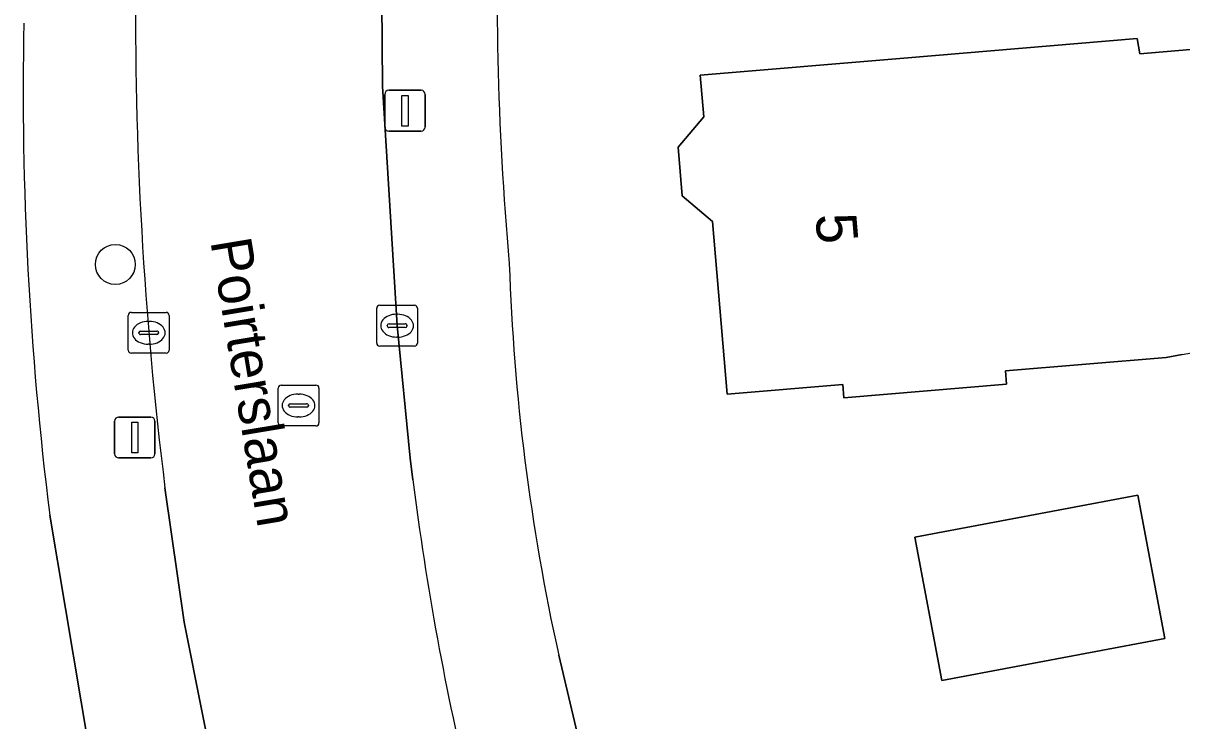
# Model space of a CAD drawing. Extents: x 161347 to 161881, y 382161 to 382804.
# Drawn here: x 161469.37 to 161497.74, y 382343.81 to 382360.88 of the extents above; entities that cross this region are included whole.
import ezdxf

# ---------------------------------------------------------------- set-up
doc = ezdxf.new("R2010")
doc.units = 0
for name, color, linetype in [('IMGEO_Boom', 7, 'Continuous'), ('IMGEO_Erf', 7, 'Continuous'), ('IMGEO_Kolk', 7, 'Continuous'), ('IMGEO_Lichtmast', 7, 'Continuous'), ('IMGEO_Openbare_ruimte_label', 7, 'Continuous'), ('IMGEO_Pand', 7, 'Continuous'), ('IMGEO_Pand_nummerreeks', 7, 'Continuous'), ('IMGEO_Rijbaan_lokaal_open', 7, 'Continuous'), ('IMGEO_Rioolput', 7, 'Continuous'), ('IMGEO_Voetpad_open', 7, 'Continuous')]:
    doc.layers.add(name, color=color, linetype=linetype)

msp = doc.modelspace()

# ---------------------------------------------------------------- linework, layer by layer
at = {"layer": 'IMGEO_Boom'}
msp.add_circle((161471.631, 382354.973), 0.489, dxfattribs=at)
at = {"layer": 'IMGEO_Erf'}
for points in [[(161497.75, 382352.769), (161497.358, 382352.698), (161493.425, 382352.37), (161493.453, 382352.045), (161489.468, 382351.71), (161489.441, 382352.035), (161486.61, 382351.797), (161486.255, 382356.023), (161485.507, 382356.655), (161485.408, 382357.84), (161486.037, 382358.585), (161485.952, 382359.604), (161490.935, 382360.023), (161496.653, 382360.502), (161496.711, 382360.131), (161498.911, 382360.315)], [(161471.178, 382341.99), (161470.024, 382348.841)], [(161482.485, 382345.416), (161483.643, 382340.539), (161484.991, 382335.711)]]:
    msp.add_lwpolyline(points, dxfattribs=at)
msp.add_lwpolyline([(161497.326, 382345.818), (161491.863, 382344.795), (161491.206, 382348.304), (161496.669, 382349.327)], close=True, dxfattribs=at)
for centre, radius, start, end in [((161557.326, 382361.781), 76.351, 177.58362, 185.0968), ((161553.635, 382359.287), 84.261, 178.91872, 187.12135), ((161533.467, 382356.71), 52.218, 181.8793, 192.4914)]:
    msp.add_arc(centre, radius, start, end, dxfattribs=at)
at = {"layer": 'IMGEO_Kolk'}
for p, q in [((161478.104, 382353.975), (161478.956, 382353.975)), ((161471.948, 382352.875), (161471.948, 382353.727)), ((161472.023, 382353.801), (161472.875, 382353.801)), ((161472.949, 382353.727), (161472.949, 382352.875)), ((161478.029, 382353.049), (161478.029, 382353.901)), ((161478.517, 382353.755), (161478.542, 382353.755)), ((161479.03, 382353.901), (161479.03, 382353.049)), ((161472.436, 382353.581), (161472.461, 382353.581)), ((161478.288, 382353.469), (161478.288, 382353.481)), ((161478.726, 382353.432), (161478.328, 382353.432)), ((161478.331, 382353.518), (161478.729, 382353.518)), ((161478.772, 382353.481), (161478.772, 382353.469)), ((161472.207, 382353.295), (161472.207, 382353.307)), ((161472.645, 382353.258), (161472.247, 382353.258)), ((161472.25, 382353.344), (161472.648, 382353.344)), ((161472.691, 382353.307), (161472.691, 382353.295)), ((161478.54, 382353.195), (161478.515, 382353.195)), ((161472.459, 382353.021), (161472.434, 382353.021)), ((161478.956, 382352.975), (161478.104, 382352.975)), ((161472.875, 382352.801), (161472.023, 382352.801))]:
    msp.add_line(p, q, dxfattribs=at)
for points in [[(161478.104, 382353.975), (161478.956, 382353.975)], [(161471.948, 382352.875), (161471.948, 382353.727)], [(161472.023, 382353.801), (161472.875, 382353.801)], [(161472.949, 382353.727), (161472.949, 382352.875)], [(161478.029, 382353.049), (161478.029, 382353.901)], [(161479.03, 382353.901), (161479.03, 382353.049)], [(161478.956, 382352.975), (161478.104, 382352.975)], [(161472.875, 382352.801), (161472.023, 382352.801)]]:
    msp.add_lwpolyline(points, dxfattribs=at)
for centre, radius, start, end in [((161478.106, 382353.899), 0.0765, 91.552, 178.448), ((161478.106, 382353.899), 0.0765, 91.552, 178.448), ((161478.954, 382353.899), 0.0765, 1.552, 88.448), ((161478.954, 382353.899), 0.0765, 1.552, 88.448), ((161472.025, 382353.725), 0.0765, 91.552, 178.448), ((161472.025, 382353.725), 0.0765, 91.552, 178.448), ((161472.873, 382353.725), 0.0765, 1.552, 88.448), ((161472.873, 382353.725), 0.0765, 1.552, 88.448), ((161478.328, 382353.478), 0.0403, 85.8775, 175.7526), ((161478.325, 382353.468), 0.0366, 178.938, 274.7102), ((161478.729, 382353.475), 0.043, 264.8664, 352.4533), ((161478.733, 382353.48), 0.0386, 1.7309, 96.639), ((161472.247, 382353.304), 0.0403, 85.8775, 175.7526), ((161472.244, 382353.294), 0.0366, 178.938, 274.7102), ((161472.648, 382353.301), 0.043, 264.8664, 352.4533), ((161472.652, 382353.306), 0.0386, 1.7309, 96.639), ((161472.025, 382352.877), 0.0765, 181.552, 268.448), ((161472.025, 382352.877), 0.0765, 181.552, 268.448), ((161472.873, 382352.877), 0.0765, 271.552, 358.448), ((161472.873, 382352.877), 0.0765, 271.552, 358.448), ((161478.106, 382353.051), 0.0765, 181.552, 268.448), ((161478.106, 382353.051), 0.0765, 181.552, 268.448), ((161478.954, 382353.051), 0.0765, 271.552, 358.448), ((161478.954, 382353.051), 0.0765, 271.552, 358.448)]:
    msp.add_arc(centre, radius, start, end, dxfattribs=at)
for centre, major_axis, ratio, start_param, end_param in [((161478.516, 382353.475), (-0.387, 0.002), 0.722429, 4.712389, 7.853982), ((161478.541, 382353.475), (-0.39, 0.002), 0.717154, 1.570796, 4.712389), ((161472.435, 382353.301), (-0.387, 0.002), 0.722429, 4.712389, 7.853982), ((161472.46, 382353.301), (-0.39, 0.002), 0.717154, 1.570796, 4.712389)]:
    msp.add_ellipse(centre, major_axis=major_axis, ratio=ratio, start_param=start_param, end_param=end_param, dxfattribs=at)
at = {"layer": 'IMGEO_Lichtmast'}
for p, q in [((161478.227, 382358.335), (161478.227, 382359.135)), ((161478.227, 382359.135), (161478.227, 382358.335)), ((161478.327, 382359.235), (161479.117, 382359.235)), ((161479.117, 382359.235), (161478.327, 382359.235)), ((161479.217, 382359.135), (161479.217, 382358.335)), ((161479.217, 382358.335), (161479.217, 382359.135)), ((161479.117, 382358.235), (161478.327, 382358.235)), ((161478.327, 382358.235), (161479.117, 382358.235)), ((161471.611, 382350.34), (161471.611, 382351.14)), ((161471.611, 382351.14), (161471.611, 382350.34)), ((161471.711, 382351.24), (161472.501, 382351.24)), ((161472.501, 382351.24), (161471.711, 382351.24)), ((161472.601, 382351.14), (161472.601, 382350.34)), ((161472.601, 382350.34), (161472.601, 382351.14)), ((161472.501, 382350.24), (161471.711, 382350.24)), ((161471.711, 382350.24), (161472.501, 382350.24))]:
    msp.add_line(p, q, dxfattribs=at)
for points in [[(161478.647, 382359.11), (161478.797, 382359.11), (161478.797, 382358.36), (161478.647, 382358.36), (161478.647, 382359.11)], [(161472.031, 382351.115), (161472.181, 382351.115), (161472.181, 382350.365), (161472.031, 382350.365), (161472.031, 382351.115)]]:
    msp.add_lwpolyline(points, dxfattribs=at)
for centre, start, end in [((161478.327, 382359.135), 90, 180), ((161478.327, 382359.135), 90, 180), ((161479.117, 382359.135), 0, 90), ((161479.117, 382359.135), 360, 90), ((161478.327, 382358.335), 180, 270), ((161478.327, 382358.335), 180, 270), ((161479.117, 382358.335), 270, 0), ((161479.117, 382358.335), 270, 0), ((161471.711, 382351.14), 90, 180), ((161471.711, 382351.14), 90, 180), ((161472.501, 382351.14), 0, 90), ((161472.501, 382351.14), 360, 90), ((161471.711, 382350.34), 180, 270), ((161471.711, 382350.34), 180, 270), ((161472.501, 382350.34), 270, 0), ((161472.501, 382350.34), 270, 0)]:
    msp.add_arc(centre, 0.1, start, end, dxfattribs=at)
at = {"layer": 'IMGEO_Pand'}
for points in [[(161497.75, 382352.769), (161497.752, 382352.769), (161499.52, 382353.085), (161499.257, 382356.205), (161498.911, 382360.315), (161496.711, 382360.131), (161496.653, 382360.502), (161490.935, 382360.023), (161485.952, 382359.604), (161486.037, 382358.585), (161485.408, 382357.84), (161485.507, 382356.655), (161486.255, 382356.023), (161486.61, 382351.797), (161489.441, 382352.035), (161489.468, 382351.71), (161493.453, 382352.045), (161493.425, 382352.37), (161497.358, 382352.698)], [(161491.863, 382344.795), (161497.326, 382345.818), (161496.669, 382349.327), (161491.206, 382348.304)]]:
    msp.add_lwpolyline(points, close=True, dxfattribs=at)
at = {"layer": 'IMGEO_Rijbaan_lokaal_open'}
for points in [[(161478.913, 382349.703), (161478.847, 382350.23), (161478.529, 382353.479), (161478.171, 382359.336), (161478.141, 382363.489)], [(161472.846, 382349.505), (161473.315, 382346.221), (161474.229, 382341.636)]]:
    msp.add_lwpolyline(points, dxfattribs=at)
for centre, radius, start, end in [((161565.952, 382361.125), 93.828, 179.39336, 187.11372), ((161550.911, 382358.887), 72.581, 187.26923, 193.48629)]:
    msp.add_arc(centre, radius, start, end, dxfattribs=at)
at = {"layer": 'IMGEO_Rioolput'}
for p, q in [((161475.69, 382352.021), (161476.542, 382352.021)), ((161475.615, 382351.095), (161475.615, 382351.947)), ((161476.103, 382351.801), (161476.128, 382351.801)), ((161476.616, 382351.947), (161476.616, 382351.095)), ((161475.874, 382351.515), (161475.874, 382351.527)), ((161476.312, 382351.478), (161475.914, 382351.478)), ((161475.917, 382351.564), (161476.315, 382351.564)), ((161476.358, 382351.527), (161476.358, 382351.515)), ((161476.126, 382351.241), (161476.101, 382351.241)), ((161476.542, 382351.021), (161475.69, 382351.021))]:
    msp.add_line(p, q, dxfattribs=at)
for points in [[(161475.69, 382352.021), (161476.542, 382352.021)], [(161475.615, 382351.095), (161475.615, 382351.947)], [(161476.616, 382351.947), (161476.616, 382351.095)], [(161476.542, 382351.021), (161475.69, 382351.021)]]:
    msp.add_lwpolyline(points, dxfattribs=at)
for centre, radius, start, end in [((161475.692, 382351.945), 0.0765, 91.552, 178.448), ((161475.692, 382351.945), 0.0765, 91.552, 178.448), ((161476.54, 382351.945), 0.0765, 1.552, 88.448), ((161476.54, 382351.945), 0.0765, 1.552, 88.448), ((161475.914, 382351.524), 0.0403, 85.8775, 175.7526), ((161475.911, 382351.514), 0.0366, 178.938, 274.7102), ((161476.315, 382351.521), 0.043, 264.8664, 352.4533), ((161476.319, 382351.526), 0.0386, 1.7309, 96.639), ((161475.692, 382351.097), 0.0765, 181.552, 268.448), ((161475.692, 382351.097), 0.0765, 181.552, 268.448), ((161476.54, 382351.097), 0.0765, 271.552, 358.448), ((161476.54, 382351.097), 0.0765, 271.552, 358.448)]:
    msp.add_arc(centre, radius, start, end, dxfattribs=at)
for centre, major_axis, ratio, start_param, end_param in [((161476.102, 382351.521), (-0.387, 0.002), 0.722429, 4.712389, 7.853982), ((161476.127, 382351.521), (-0.39, 0.002), 0.717154, 1.570796, 4.712389)]:
    msp.add_ellipse(centre, major_axis=major_axis, ratio=ratio, start_param=start_param, end_param=end_param, dxfattribs=at)
at = {"layer": 'IMGEO_Voetpad_open'}
for points in [[(161480.29, 382392.675), (161480.197, 382391.427), (161480.126, 382390.67), (161479.848, 382387.77), (161479.664, 382385.857), (161479.39, 382383.203), (161478.467, 382374.26), (161478.179, 382367.212), (161478.141, 382363.489), (161478.171, 382359.336), (161478.529, 382353.479), (161478.847, 382350.23), (161478.913, 382349.703)], [(161474.229, 382341.636), (161473.315, 382346.221), (161472.846, 382349.505)], [(161470.024, 382348.841), (161471.178, 382341.99)], [(161483.643, 382340.539), (161482.485, 382345.416)]]:
    msp.add_lwpolyline(points, dxfattribs=at)
for centre, radius, start, end in [((161557.326, 382361.781), 76.351, 177.58362, 185.0968), ((161565.952, 382361.125), 93.828, 179.39336, 187.11372), ((161553.635, 382359.287), 84.261, 178.91872, 187.12135), ((161533.467, 382356.71), 52.218, 181.8793, 192.4914), ((161550.911, 382358.887), 72.581, 187.26923, 193.48629)]:
    msp.add_arc(centre, radius, start, end, dxfattribs=at)

# ---------------------------------------------------------------- texts
at = {"layer": 'IMGEO_Openbare_ruimte_label'}
msp.add_text('Poirterslaan', height=1, rotation=279.4435, dxfattribs=at).set_placement((161473.954, 382355.542))
at = {"layer": 'IMGEO_Pand_nummerreeks'}
msp.add_text('5', height=1, rotation=274.8184, dxfattribs=at).set_placement((161488.769, 382356.187))

doc.saveas('drawing.dxf')
